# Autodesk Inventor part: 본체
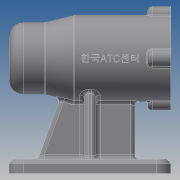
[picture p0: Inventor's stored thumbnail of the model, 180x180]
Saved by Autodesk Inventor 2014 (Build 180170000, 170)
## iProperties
Created: 2019-07
Part Number: 본체
Material: Generic
Document SubType Name: Modeling
Designer: kb541-07
Density: 1 g/cm^3
Appearance: Default
Mass: 238.662 g
Surface Area: 654.094 cm^2
Volume: 238.662 cm^3
Author: kb541-07
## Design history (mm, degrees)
sketch "스케치1"
  geometry: L1 (-56, 0)-(56, 0); L2 (-56, 0)-(-56, 25); L3 (-56, 25)-(-31, 25); L4 (-31, 25)-(-11, 30); L5 (-11, 30)-(56, 30); L6 (56, 30)-(56, 0); 2 further points
  constraints: 12 end point, 2 perpendicular, 1 coincident, 1 horizontal, 1 midpoint, 1 parallel, 1 vertical
  dimensions: "d0" = 112 distance of L1.start L1.end; "d1" = 50 diameter of L3 L1; "d2" = 60 diameter of L5 L1; "d3" = 25 distance of L2.end L3.end; "d4" = 45 horizontal distance of L2.end L4.end
revolve "회전1" sketch "스케치1" stored, may be unused: angle "d5" = 90 deg
sketch "스케치2"
  geometry: C1 r 6 at (0, 30); C2 r 6 at (-30, 0); C3 r 6 at (0, -30); C4 r 6 at (30, 0); A1 r 30 centre (0, 0) between (0, 30) and (-30, 0) reference
  constraints: 4 centre point, 4 point on circle, 3 equal radius, 2 horizontal alignment, 2 vertical alignment
  dimensions: "d6" = 12 diameter of C1
extrude "돌출1" join sketch "스케치2" distance "d7" = 16; taper "d8" = 0 deg
sketch "스케치3"
  geometry: L1 (-56, -25)-(-56, 25) reference; L2 (-56, 25)-(-31, 25) reference; L3 (-31, 25)-(-11, 30) reference; L4 (-11, 30)-(40, 30) reference; L5 (40, 30)-(40, 36) reference; L6 (40, 36)-(56, 36) reference; L7 (56, 36)-(56, -36) reference; L8 (56, -36)-(40, -36) reference; L9 (40, -36)-(40, -30) reference; L10 (40, -30)-(-11, -30) reference; L11 (-11, -30)-(-31, -25) reference; L12 (-31, -25)-(-56, -25) reference; L13 (-56, 0)-(56, 0); L14 (-50, 0)-(-50, 10.5); L15 (-50, 10.5)-(-47, 10.5); L16 (-47, 10.5)-(-47, 16); L17 (-47, 16)-(-43, 16); L18 (-43, 16)-(-43, 17.5); L19 (-43, 17.5)-(-25, 17.5); L20 (-25, 17.5)-(-25, 21); L21 (-25, 21)-(-13, 21); L22 (-13, 21)-(-13, 24); L23 (-13, 24)-(41, 24); L24 (41, 24)-(41, 21); L25 (41, 21)-(56, 21); L26 (56, 21)-(56, 0); L27 (56, 5.97)-(56, 29.4) reference; 1 further point
  constraints: 28 end point, 7 perpendicular, 5 parallel, 2 midpoint, 2 point on line, 1 collinear
  dimensions: "d9" = 15 distance of L24.end L25.end; "d10" = 48 diameter of L23 L13; "d11" = 42 diameter of L25 L13; "d12" = 42 diameter of L21 L13; "d13" = 21 diameter of L15 L13; "d14" = 32 diameter of L17 L13; "d15" = 35 diameter of L19 L13; "d16" = 3 distance of L14.end L15.end; "d17" = 4 distance of L16.end L17.end; "d18" = 18 distance of L18.end L19.end; "d19" = 12 distance of L20.end L21.end; "d21" = 54 distance of L22.end L23.end
revolve "회전2" sketch "스케치3" stored, may be unused: angle "d22" = 90 deg
sketch "스케치5"
  geometry: L1 (-56, -70)-(56, -70); L2 (56, -70)-(56, -80); L3 (56, -80)-(-56, -80); L4 (-56, -80)-(-56, -70); L5 (-56, -25)-(-56, 25) reference; L6 (-56, 25)-(-31, 25) reference; L7 (-31, 25)-(-11, 30) reference; L8 (-11, 30)-(40, 30) reference; L9 (40, 30)-(40, 36) reference; L10 (40, 36)-(56, 36) reference; L11 (56, 36)-(56, 21) reference; L12 (56, 21)-(41, 21) reference; L13 (41, 21)-(41, 24) reference; L14 (41, 24)-(-13, 24) reference; L15 (-13, 24)-(-13, 21) reference; L16 (-13, 21)-(-25, 21) reference; L17 (-25, 21)-(-25, 17.5) reference; L18 (-25, 17.5)-(-43, 17.5) reference; L19 (-43, 17.5)-(-43, 16) reference; L20 (-43, 16)-(-47, 16) reference; L21 (-47, 16)-(-47, 10.5) reference; L22 (-47, 10.5)-(-50, 10.5) reference; L23 (-50, 10.5)-(-50, -10.5) reference; L24 (-50, -10.5)-(-47, -10.5) reference; L25 (-47, -10.5)-(-47, -16) reference; L26 (-47, -16)-(-43, -16) reference; L27 (-43, -16)-(-43, -17.5) reference; L28 (-43, -17.5)-(-25, -17.5) reference; L29 (-25, -17.5)-(-25, -21) reference; L30 (-25, -21)-(-13, -21) reference; L31 (-13, -21)-(-13, -24) reference; L32 (-13, -24)-(41, -24) reference; L33 (41, -24)-(41, -21) reference; L34 (41, -21)-(56, -21) reference; L35 (56, -21)-(56, -36) reference; L36 (56, -36)-(40, -36) reference; L37 (40, -36)-(40, -30) reference; L38 (40, -30)-(-11, -30) reference; L39 (-11, -30)-(-31, -25) reference; L40 (-31, -25)-(-56, -25) reference; L41 (56, 21)-(56, -21) reference; L42 (-56, -25)-(-56, 25) reference; L43 (-56, 0)-(56, 0); 1 further point
  constraints: 10 end point, 2 midpoint, 2 parallel, 1 collinear, 1 horizontal, 1 perpendicular
  dimensions: "d24" = 10 distance of L1.end L2.end; "d25" = 112 distance of L2.end L3.end; "d26" = 80 distance between parallel lines of L3 L43
extrude "돌출2" join sketch "스케치5" stored distance "d27" = 70; taper "d28" = 0 deg
node "작업 평면2"
sketch "스케치6"
  geometry: L1 (65, -70)-(-5, -70) reference; L2 (30, 0)-(30, -70); L3 (2, -70)-(10.346, -22.666); L4 (58, -70)-(49.654, -22.666); L5 (2, -70)-(58, -70); A1 r 30 centre (30, 0) between (10.346, -22.666) and (49.654, -22.666); 1 further point
  constraints: 8 end point, 2 point on circle, 2 symmetric about line, 1 centre point, 1 collinear, 1 midpoint, 1 point on line, 3 other
  dimensions: "d30" = 7 distance of L1.end L3.start; "d31" = 100 deg angle of L3 L1
extrude "돌출3" join sketch "스케치6" stored distance "d32" = 8; taper "d33" = 0 deg
sketch "스케치7"
  geometry: L1 (-56, -25)-(-56, 25) reference; L2 (-56, 25)-(-31, 25) reference; L3 (-31, 25)-(-11, 30) reference; L4 (-11, 30)-(40, 30) reference; L5 (40, 30)-(40, 36) reference; L6 (40, 36)-(56, 36) reference; L7 (56, 36)-(56, 21) reference; L8 (56, 21)-(41, 21) reference; L9 (41, 21)-(41, 24) reference; L10 (41, 24)-(-13, 24) reference; L11 (-13, 24)-(-13, 21) reference; L12 (-13, 21)-(-25, 21) reference; L13 (-25, 21)-(-25, 17.5) reference; L14 (-25, 17.5)-(-43, 17.5) reference; L15 (-43, 17.5)-(-43, 16) reference; L16 (-43, 16)-(-47, 16) reference; L17 (-47, 16)-(-47, 10.5) reference; L18 (-47, 10.5)-(-50, 10.5) reference; L19 (-50, 10.5)-(-50, -10.5) reference; L20 (-50, -10.5)-(-47, -10.5) reference; L21 (-47, -10.5)-(-47, -16) reference; L22 (-47, -16)-(-43, -16) reference; L23 (-43, -16)-(-43, -17.5) reference; L24 (-43, -17.5)-(-25, -17.5) reference; L25 (-25, -17.5)-(-25, -21) reference; L26 (-25, -21)-(-13, -21) reference; L27 (-13, -21)-(-13, -24) reference; L28 (-13, -24)-(41, -24) reference; L29 (41, -24)-(41, -21) reference; L30 (41, -21)-(56, -21) reference; L31 (56, -21)-(56, -36) reference; L32 (56, -36)-(40, -36) reference; L33 (40, -36)-(40, -30) reference; L34 (40, -30)-(4, -30) reference; L35 (4, -30)-(4, -70) reference; L36 (4, -70)-(56, -70) reference; L37 (56, -70)-(56, -80) reference; L38 (56, -80)-(-56, -80) reference; L39 (-56, -80)-(-56, -70) reference; L40 (-56, -70)-(-4, -70) reference; L41 (-4, -70)-(-4, -30) reference; L42 (-4, -30)-(-11, -30) reference; L43 (-11, -30)-(-31, -25) reference; L44 (-31, -25)-(-56, -25) reference; L45 (-36, -70)-(-20.57, -27.607); 1 further point
  constraints: 2 end point, 2 point on line
  dimensions: "d34" = 20 distance of L39.end L45.start; "d35" = 110 deg angle of L45 L40
feature "리브1" sketch "스케치7" dims "d36" = 1, "d37" = 8, "d38" = 0, "d39" = 0, "d40" = 1, "d41" = 1
sketch "스케치8"
  geometry: L1 (-56, -25)-(-56, 25) reference; L2 (-56, 25)-(-31, 25) reference; L3 (-31, 25)-(-11, 30) reference; L4 (-11, 30)-(40, 30) reference; L5 (40, 30)-(40, 36) reference; L6 (40, 36)-(56, 36) reference; L7 (56, 36)-(56, 21) reference; L8 (56, 21)-(41, 21) reference; L9 (41, 21)-(41, 24) reference; L10 (41, 24)-(-13, 24) reference; L11 (-13, 24)-(-13, 21) reference; L12 (-13, 21)-(-25, 21) reference; L13 (-25, 21)-(-25, 17.5) reference; L14 (-25, 17.5)-(-43, 17.5) reference; L15 (-43, 17.5)-(-43, 16) reference; L16 (-43, 16)-(-47, 16) reference; L17 (-47, 16)-(-47, 10.5) reference; L18 (-47, 10.5)-(-50, 10.5) reference; L19 (-50, 10.5)-(-50, -10.5) reference; L20 (-50, -10.5)-(-47, -10.5) reference; L21 (-47, -10.5)-(-47, -16) reference; L22 (-47, -16)-(-43, -16) reference; L23 (-43, -16)-(-43, -17.5) reference; L24 (-43, -17.5)-(-25, -17.5) reference; L25 (-25, -17.5)-(-25, -21) reference; L26 (-25, -21)-(-13, -21) reference; L27 (-13, -21)-(-13, -24) reference; L28 (-13, -24)-(41, -24) reference; L29 (41, -24)-(41, -21) reference; L30 (41, -21)-(56, -21) reference; L31 (56, -21)-(56, -36) reference; L32 (56, -36)-(40, -36) reference; L33 (40, -36)-(40, -30) reference; L34 (40, -30)-(4, -30) reference; L35 (4, -30)-(4, -70) reference; L36 (4, -70)-(56, -70) reference; L37 (56, -70)-(56, -80) reference; L38 (56, -80)-(-56, -80) reference; L39 (-56, -80)-(-56, -70) reference; L40 (-56, -70)-(-36, -70) reference; L41 (-36, -70)-(-20.57, -27.607) reference; L42 (-20.57, -27.607)-(-31, -25) reference; L43 (-31, -25)-(-56, -25) reference; L44 (4, -30)-(40, -30) reference; L45 (31, -30)-(31, -70); 1 further point
  constraints: 2 end point, 2 point on line, 1 perpendicular
  dimensions: "d42" = 25 distance between parallel lines of L37 L45
feature "리브2" sketch "스케치8" dims "d43" = 1, "d44" = 8, "d45" = 0, "d46" = 0, "d47" = 1, "d48" = 1
fillet "모깎기1" dims "d51" = 10
sketch "스케치10"
  geometry: C1 r 3 at (0, 60); C2 r 3 at (92, 60); C3 r 3 at (0, 10); C4 r 3 at (92, 10); A1 r 10 centre (0, 60) between (0, 70) and (-10, 60) reference; A2 r 10 centre (0, 10) between (-10, 10) and (0, 0) reference; A3 r 10 centre (92, 10) between (92, 0) and (102, 10) reference; A4 r 10 centre (92, 60) between (102, 60) and (92, 70) reference; 1 further point
  constraints: 4 centre point, 4 coincident, 3 equal radius
  dimensions: "d52" = 6 diameter of C1
extrude "돌출4" cut sketch "스케치10" stored distance "d53" = 8; taper "d54" = 0 deg
fillet "모깎기2" dims "d55" = 3
fillet "모깎기3" dims "d56" = 0.3
fillet "모깎기4" dims "d57" = 3
fillet "모깎기5" dims "d58" = 1
fillet "모깎기6" dims "d59" = 3
sketch "스케치11"
  geometry: C1 r 21 at (30, 0) reference; A1 r 30 centre (30, 0) between (23.229, 29.226) and (0.774, 6.771) reference; A2 r 30 centre (30, 0) between (59.226, 6.771) and (36.771, 29.226) reference; 2 further points
  constraints: 2 vertical alignment, 1 coincident, 3 other
hole "구멍1" sketch "스케치11" at (30, 30) diameter "d60" = 3.242; stored, may be unused: countersink angle "d64" = 90 deg, drill point angle "d66" = 118 deg; dims "d61" = 8, "d62" = 4, "d63" = 2, "d65" = 11
chamfer "모따기1" distance "d70" = 1; stored, may be unused: second distance "d71" = 2, angle "d72" = 45 deg
node "작업 평면3"
sketch "스케치12"
  geometry: L1 (56, 6.771)-(56, 29.226) reference; L2 (56, -29.226)-(56, -6.771) reference; L3 (56, 5.998)-(56, -5.998) reference; L4 (-56, -15)-(-56, 15) reference; L5 (-56, 0)-(56, 0); 2 further points
  constraints: 2 end point, 2 midpoint, 1 point on line, 1 other
  dimensions: "d74" = 42 distance from line of L1 point (14, 0)
feature "엠보싱1" sketch "스케치12" dims "d0" = 112, "d1" = 50, "d2" = 60, "d3" = 25, "d4" = 45, "d75" = 0.5, "d76" = 0
fillet "모깎기7" dims "d77" = 3
chamfer "모따기2" distance "d78" = 3; stored, may be unused: second distance "d79" = 2, angle "d80" = 45 deg
node "솔리드1"
pattern_circular "원형 패턴1" dims angle "d68" = 360 deg
node "절단 모서리 투영1"
node "절단 모서리 투영2"
node "절단 모서리 투영3"
node "절단 모서리 투영4"
other parameters: "d29" = -56, "d73" = 116.5
